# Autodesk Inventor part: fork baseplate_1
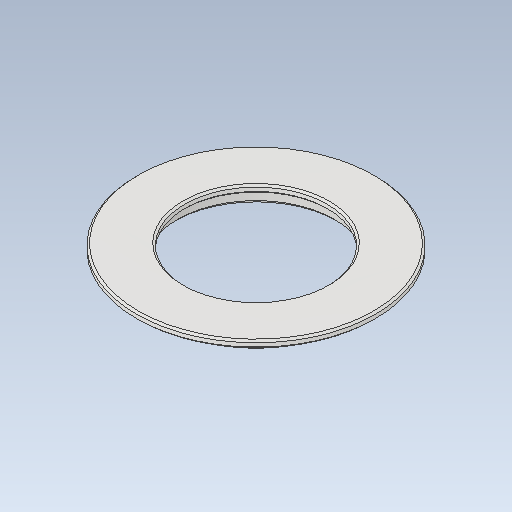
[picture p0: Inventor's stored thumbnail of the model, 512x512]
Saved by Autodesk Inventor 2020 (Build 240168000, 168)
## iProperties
Created: 2017-09
Part Number: fork baseplate_1
Material: Ogólny
Document SubType Name: Modeling
Designer: Tomasz
Density: 1 g/cm^3
Appearance: Domyślna
Sending System: SolidWorks 2017
Last Author: Tomasz
Last Saved: 2017-09-17
Source: fork baseplate_1
Author: Tomasz
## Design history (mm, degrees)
feature "Faza5"
node "Bryła1"
